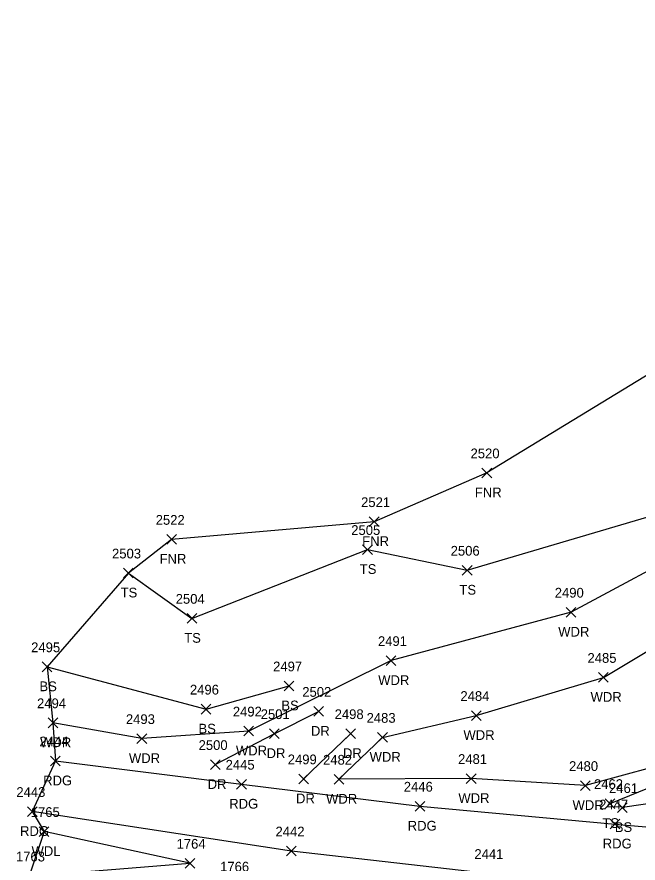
# Model space of a CAD drawing. Extents: x 1633660 to 1636532, y 388643 to 392631.
# Drawn here: x 1634327.7 to 1634455.1, y 389113.6 to 389287.2 of the extents above; entities that cross this region are included whole.
import ezdxf

# ---------------------------------------------------------------- set-up
doc = ezdxf.new("R2010")
doc.units = 0
for name, color, linetype in [('L_A', 7, 'Continuous'), ('L_I', 7, 'Continuous'), ('L_TIC', 7, 'Continuous'), ('LAWA', 7, 'Continuous'), ('LELB', 7, 'Continuous'), ('LFNC', 7, 'Continuous'), ('LSOGP', 7, 'Continuous'), ('P_A', 7, 'Continuous'), ('P_I', 7, 'Continuous'), ('P_TIC', 7, 'Continuous'), ('PEU', 7, 'Continuous'), ('R_A', 7, 'Continuous'), ('R_I', 7, 'Continuous'), ('R_TIC', 7, 'Continuous'), ('RDP', 7, 'Continuous')]:
    doc.layers.add(name, color=color, linetype=linetype)

msp = doc.modelspace()

# ---------------------------------------------------------------- linework, layer by layer
at = {"layer": 'L_TIC'}
for points in [[(1634423.09, 389192.65), (1634425.09, 389194.65)], [(1634425.09, 389192.65), (1634423.09, 389194.65)], [(1634399.99, 389182.64), (1634401.99, 389184.64)], [(1634401.99, 389182.64), (1634399.99, 389184.64)], [(1634358.44, 389179.01), (1634360.44, 389181.01)], [(1634360.44, 389179.01), (1634358.44, 389181.01)], [(1634398.62, 389176.92), (1634400.62, 389178.92)], [(1634400.62, 389176.92), (1634398.62, 389178.92)], [(1634349.57, 389172.1), (1634351.57, 389174.1)], [(1634351.57, 389172.1), (1634349.57, 389174.1)], [(1634419.06, 389172.67), (1634421.06, 389174.67)], [(1634421.06, 389172.67), (1634419.06, 389174.67)], [(1634440.37, 389164.06), (1634442.37, 389166.06)], [(1634442.37, 389164.06), (1634440.37, 389166.06)], [(1634362.62, 389162.8), (1634364.62, 389164.8)], [(1634364.62, 389162.8), (1634362.62, 389164.8)], [(1634403.45, 389154.13), (1634405.45, 389156.13)], [(1634405.45, 389154.13), (1634403.45, 389156.13)], [(1634332.9, 389152.86), (1634334.9, 389154.86)], [(1634334.9, 389152.86), (1634332.9, 389154.86)], [(1634446.99, 389150.68), (1634448.99, 389152.68)], [(1634448.99, 389150.68), (1634446.99, 389152.68)], [(1634382.52, 389148.93), (1634384.52, 389150.93)], [(1634384.52, 389148.93), (1634382.52, 389150.93)], [(1634365.51, 389144.17), (1634367.51, 389146.17)], [(1634367.51, 389144.17), (1634365.51, 389146.17)], [(1634420.93, 389142.86), (1634422.93, 389144.86)], [(1634422.93, 389142.86), (1634420.93, 389144.86)], [(1634334.11, 389141.37), (1634336.11, 389143.37)], [(1634336.11, 389141.37), (1634334.11, 389143.37)], [(1634374.26, 389139.67), (1634376.26, 389141.67)], [(1634376.26, 389139.67), (1634374.26, 389141.67)], [(1634352.33, 389138.12), (1634354.33, 389140.12)], [(1634354.33, 389138.12), (1634352.33, 389140.12)], [(1634401.69, 389138.38), (1634403.69, 389140.38)], [(1634403.69, 389138.38), (1634401.69, 389140.38)], [(1634392.76, 389129.78), (1634394.76, 389131.78)], [(1634394.76, 389129.78), (1634392.76, 389131.78)], [(1634419.88, 389129.93), (1634421.88, 389131.93)], [(1634421.88, 389129.93), (1634419.88, 389131.93)], [(1634443.3, 389128.49), (1634445.3, 389130.49)], [(1634445.3, 389128.49), (1634443.3, 389130.49)], [(1634448.37, 389124.79), (1634450.37, 389126.79)], [(1634450.37, 389124.79), (1634448.37, 389126.79)], [(1634450.89, 389123.96), (1634452.89, 389125.96)], [(1634452.89, 389123.96), (1634450.89, 389125.96)], [(1634332.3, 389119.05), (1634334.3, 389121.05)], [(1634334.3, 389119.05), (1634332.3, 389121.05)], [(1634362.2, 389112.54), (1634364.2, 389114.54)], [(1634364.2, 389112.54), (1634362.2, 389114.54)]]:
    msp.add_lwpolyline(points, dxfattribs=at)
at = {"layer": 'LAWA'}
for points in [[(1634531.92, 389222.94), (1634492.3, 389196.57), (1634468.38, 389179.57), (1634441.37, 389165.06), (1634404.45, 389155.13), (1634375.26, 389140.67), (1634353.33, 389139.12), (1634335.11, 389142.37)], [(1634491.48, 389177.58), (1634496.72, 389171.03), (1634478.3, 389151.83), (1634478.08, 389147.81), (1634458.37, 389133.34), (1634444.3, 389129.49), (1634420.88, 389130.93), (1634393.76, 389130.78), (1634402.69, 389139.38), (1634421.93, 389143.86), (1634447.99, 389151.68), (1634468.04, 389163.74)], [(1634330.26, 389110.92), (1634363.2, 389113.54), (1634333.3, 389120.05)]]:
    msp.add_lwpolyline(points, dxfattribs=at)
at = {"layer": 'LELB'}
for points in [[(1634350.57, 389173.1), (1634363.62, 389163.8), (1634399.62, 389177.92), (1634420.06, 389173.67), (1634464.07, 389186.67), (1634489.47, 389219.41), (1634515.93, 389234.07), (1634542.34, 389257.67), (1634562.83, 389273.35), (1634574.95, 389268.71), (1634584.12, 389260.54), (1634576.6, 389275.51), (1634566.05, 389287.22)], [(1634333.9, 389153.86), (1634366.51, 389145.17), (1634383.52, 389149.93)], [(1634449.37, 389125.79), (1634461.16, 389130.62)], [(1634460.84, 389126.3), (1634451.89, 389124.96)]]:
    msp.add_lwpolyline(points, dxfattribs=at)
at = {"layer": 'LFNC'}
msp.add_lwpolyline([(1634558.9, 389281.65), (1634537.12, 389267.57), (1634504.95, 389250.1), (1634474.13, 389224.17), (1634424.09, 389193.65), (1634400.99, 389183.64), (1634359.44, 389180.01)], dxfattribs=at)
at = {"layer": 'LSOGP'}
msp.add_lwpolyline([(1634474.13, 389224.17), (1634424.09, 389193.65), (1634400.99, 389183.64), (1634359.44, 389180.01), (1634350.57, 389173.1), (1634333.9, 389153.86), (1634335.11, 389142.37), (1634335.61, 389134.54), (1634330.87, 389124.16), (1634333.3, 389120.05), (1634330.26, 389110.92)], dxfattribs=at)
at = {"layer": 'P_TIC'}
for points in [[(1634334.61, 389133.54), (1634336.61, 389135.54)], [(1634336.61, 389133.54), (1634334.61, 389135.54)], [(1634372.78, 389128.76), (1634374.78, 389130.76)], [(1634374.78, 389128.76), (1634372.78, 389130.76)], [(1634409.37, 389124.25), (1634411.37, 389126.25)], [(1634411.37, 389124.25), (1634409.37, 389126.25)], [(1634329.87, 389123.16), (1634331.87, 389125.16)], [(1634331.87, 389123.16), (1634329.87, 389125.16)], [(1634449.38, 389120.59), (1634451.38, 389122.59)], [(1634451.38, 389120.59), (1634449.38, 389122.59)], [(1634383.01, 389115.06), (1634385.01, 389117.06)], [(1634385.01, 389115.06), (1634383.01, 389117.06)]]:
    msp.add_lwpolyline(points, dxfattribs=at)
at = {"layer": 'PEU'}
for points in [[(1634335.61, 389134.54), (1634373.78, 389129.76), (1634410.37, 389125.25), (1634450.38, 389121.59), (1634496.84, 389117.53)], [(1634494.26, 389106.08), (1634473.78, 389107.86), (1634424.23, 389111.44), (1634384.01, 389116.06), (1634330.87, 389124.16)]]:
    msp.add_lwpolyline(points, dxfattribs=at)
at = {"layer": 'R_TIC'}
for points in [[(1634388.58, 389143.71), (1634390.58, 389145.71)], [(1634390.58, 389143.71), (1634388.58, 389145.71)], [(1634379.49, 389139.14), (1634381.49, 389141.14)], [(1634381.49, 389139.14), (1634379.49, 389141.14)], [(1634395.14, 389139.14), (1634397.14, 389141.14)], [(1634397.14, 389139.14), (1634395.14, 389141.14)], [(1634367.41, 389132.8), (1634369.41, 389134.8)], [(1634369.41, 389132.8), (1634367.41, 389134.8)], [(1634385.52, 389129.86), (1634387.52, 389131.86)], [(1634387.52, 389129.86), (1634385.52, 389131.86)]]:
    msp.add_lwpolyline(points, dxfattribs=at)
at = {"layer": 'RDP'}
for points in [[(1634368.41, 389133.8), (1634380.49, 389140.14), (1634389.58, 389144.71)], [(1634396.14, 389140.14), (1634386.52, 389130.86)]]:
    msp.add_lwpolyline(points, dxfattribs=at)

# ---------------------------------------------------------------- texts
at = {"layer": 'L_A'}
for s, p in [('FNR', (1634421.63, 389188.65)), ('FNR', (1634398.53, 389178.64)), ('FNR', (1634356.98, 389175.01)), ('TS', (1634398.03, 389172.92)), ('TS', (1634418.47, 389168.67)), ('TS', (1634348.98, 389168.1)), ('WDR', (1634438.73, 389160.06)), ('TS', (1634362.03, 389158.8)), ('WDR', (1634401.81, 389150.13)), ('BS', (1634332.34, 389148.86)), ('WDR', (1634445.36, 389146.68)), ('BS', (1634381.96, 389144.93)), ('BS', (1634364.95, 389140.17)), ('WDR', (1634332.47, 389137.37)), ('WDR', (1634419.29, 389138.86)), ('WDR', (1634372.63, 389135.67)), ('WDR', (1634350.69, 389134.12)), ('WDR', (1634400.05, 389134.38)), ('WDR', (1634391.12, 389125.78)), ('WDR', (1634418.25, 389125.93)), ('WDR', (1634441.66, 389124.49)), ('TS', (1634447.78, 389120.79)), ('BS', (1634450.33, 389119.96)), ('WDL', (1634330.72, 389115.05))]:
    msp.add_text(s, height=2, dxfattribs=at).set_placement(p)
at = {"layer": 'L_I'}
for s, p in [('2520', (1634420.75, 389196.65)), ('2521', (1634398.3, 389186.64)), ('2522', (1634356.18, 389183.01)), ('2505', (1634396.28, 389180.92)), ('2503', (1634347.23, 389176.1)), ('2506', (1634416.67, 389176.67)), ('2504', (1634360.28, 389166.8)), ('2490', (1634438.02, 389168.06)), ('2491', (1634401.76, 389158.13)), ('2495', (1634330.64, 389156.86)), ('2485', (1634444.73, 389154.68)), ('2497', (1634380.26, 389152.93)), ('2496', (1634363.2, 389148.17)), ('2484', (1634418.67, 389146.86)), ('2494', (1634331.85, 389145.37)), ('2492', (1634372, 389143.67)), ('2493', (1634350.07, 389142.12)), ('2483', (1634399.43, 389142.38)), ('2482', (1634390.5, 389133.78)), ('2481', (1634418.19, 389133.93)), ('2480', (1634440.95, 389132.49)), ('2462', (1634446.06, 389128.79)), ('2461', (1634449.15, 389127.96)), ('1765', (1634330.56, 389123.05)), ('1764', (1634360.46, 389116.54)), ('1763', (1634327.52, 389113.92)), ('1766', (1634369.39, 389111.85))]:
    msp.add_text(s, height=2, dxfattribs=at).set_placement(p)
at = {"layer": 'P_A'}
for p in [(1634333.1, 389129.54), (1634371.26, 389124.76), (1634407.86, 389120.25), (1634328.36, 389119.16), (1634447.86, 389116.59)]:
    msp.add_text('RDG', height=2, dxfattribs=at).set_placement(p)
at = {"layer": 'P_I'}
for s, p in [('2444', (1634332.35, 389137.54)), ('2445', (1634370.52, 389132.76)), ('2443', (1634327.61, 389127.16)), ('2446', (1634407.06, 389128.25)), ('2447', (1634447.12, 389124.59)), ('2442', (1634380.75, 389119.06)), ('2441', (1634421.54, 389114.44))]:
    msp.add_text(s, height=2, dxfattribs=at).set_placement(p)
at = {"layer": 'R_A'}
for p in [(1634388.02, 389139.71), (1634378.92, 389135.14), (1634394.58, 389135.14), (1634366.84, 389128.8), (1634384.96, 389125.86)]:
    msp.add_text('DR', height=2, dxfattribs=at).set_placement(p)
at = {"layer": 'R_I'}
for s, p in [('2502', (1634386.24, 389147.71)), ('2501', (1634377.72, 389143.14)), ('2498', (1634392.88, 389143.14)), ('2500', (1634364.98, 389136.8)), ('2499', (1634383.26, 389133.86))]:
    msp.add_text(s, height=2, dxfattribs=at).set_placement(p)

doc.saveas('drawing.dxf')
